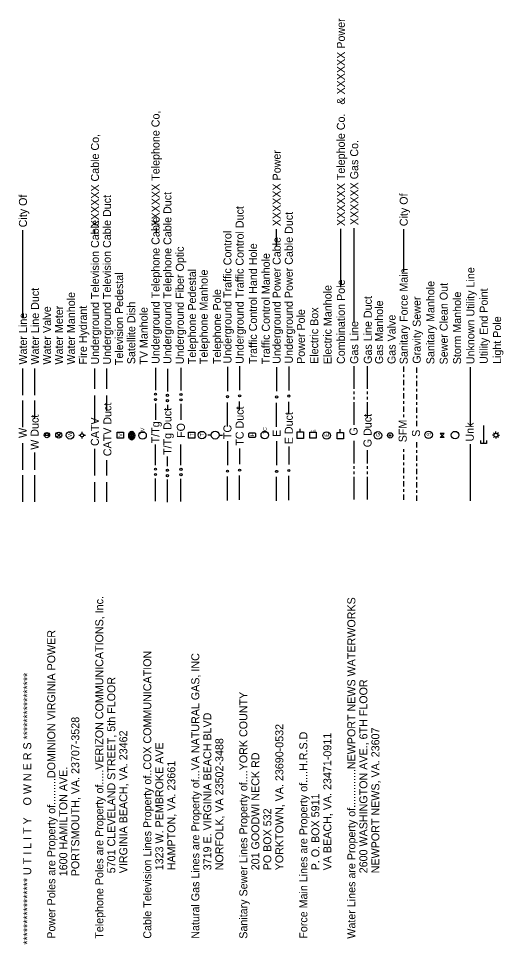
# Model space of a CAD drawing. Extents: x 3872070 to 3879223, y 293944 to 310567.
# Drawn here: x 3876716.5 to 3876898.3, y 293944.3 to 294291.3 of the extents above; entities that cross this region are included whole.
import ezdxf

# ---------------------------------------------------------------- set-up
doc = ezdxf.new("R2010")
doc.units = 0
for name, color, linetype in [('Level 3', 7, 'Continuous'), ('Level 4', 7, 'Continuous'), ('Level 5', 7, 'Continuous'), ('Level 6', 7, 'Continuous'), ('Level 61', 7, 'Continuous'), ('Level 7', 7, 'Continuous'), ('Level 8', 7, 'Continuous'), ('Level 9', 7, 'Continuous')]:
    doc.layers.add(name, color=color, linetype=linetype)

msp = doc.modelspace()

# ---------------------------------------------------------------- linework, layer by layer
at = {"layer": 'Level 4'}
for p, q in [((3876894.75, 294135.14), (3876894.18, 294135.14)), ((3876894.96, 294135.65), (3876894.56, 294136.05)), ((3876894.96, 294134.62), (3876894.56, 294134.22)), ((3876895.48, 294135.86), (3876895.48, 294136.44)), ((3876896.4, 294136.05), (3876895.99, 294135.65)), ((3876896.4, 294134.22), (3876895.99, 294134.62)), ((3876896.2, 294135.14), (3876896.78, 294135.14)), ((3876895.48, 294134.41), (3876895.48, 294133.84))]:
    msp.add_line(p, q, dxfattribs=at)
msp.add_lwpolyline([(3876828.16, 294134.02), (3876825.76, 294134.02), (3876825.76, 294136.21), (3876828.16, 294136.21)], close=True, dxfattribs=at)
for centre, radius in [((3876832.03, 294135.01), 1.41), ((3876895.48, 294135.14), 0.725)]:
    msp.add_circle(centre, radius, dxfattribs=at)
at = {"layer": 'Level 5'}
for p, q in [((3876739.08, 294135.08), (3876739.72, 294135.08)), ((3876740.33, 294135.7), (3876740.33, 294136.33)), ((3876740.96, 294135.08), (3876741.58, 294135.08)), ((3876740.33, 294133.83), (3876740.33, 294134.45))]:
    msp.add_line(p, q, dxfattribs=at)
for centre, radius in [((3876735.83, 294135.08), 1.41), ((3876740.33, 294135.08), 0.625)]:
    msp.add_circle(centre, radius, dxfattribs=at)
at = {"layer": 'Level 6'}
msp.add_lwpolyline([(3876892, 294133.12), (3876892, 294132.03), (3876889.81, 294132.03), (3876889.81, 294133.12)], dxfattribs=at)
msp.add_circle((3876851.27, 294135.04), 1.41, dxfattribs=at)
at = {"layer": 'Level 61'}
for p, q in [((3876718.18, 294179.01), (3876718.18, 294211.9)), ((3876745.18, 294210.45), (3876745.18, 294211.9)), ((3876768.24, 294210.94), (3876768.25, 294212.86)), ((3876813.29, 294205.89), (3876813.29, 294212.31)), ((3876837.36, 294190.56), (3876837.36, 294212.4)), ((3876842.36, 294177.4), (3876842.36, 294212.72)), ((3876860.92, 294196.28), (3876860.92, 294212.33)), ((3876718.18, 294150.13), (3876718.18, 294160.12)), ((3876722.68, 294150.13), (3876722.68, 294160.12)), ((3876745.18, 294152.5), (3876745.18, 294160.12)), ((3876749.68, 294152.5), (3876749.68, 294160.12)), ((3876749.68, 294156.38), (3876749.68, 294160.12)), ((3876767.88, 294160.38), (3876767.88, 294151.96)), ((3876772.34, 294159.95), (3876772.34, 294151.53)), ((3876777.43, 294160.3), (3876777.43, 294151.88)), ((3876794.85, 294160.67), (3876794.85, 294151.67)), ((3876799.41, 294161.02), (3876799.41, 294152.02)), ((3876813.29, 294160.56), (3876813.29, 294151.56)), ((3876817.84, 294160.91), (3876817.84, 294151.91)), ((3876842.36, 294152.46), (3876842.36, 294160.96)), ((3876847.36, 294152.46), (3876847.36, 294160.96)), ((3876860.91, 294158.9), (3876860.91, 294160.88)), ((3876865.9, 294158.47), (3876865.9, 294160.45)), ((3876885.91, 294138.57), (3876885.92, 294160.57)), ((3876860.91, 294156.9), (3876860.91, 294157.9)), ((3876860.91, 294153.9), (3876860.91, 294155.9)), ((3876865.9, 294156.47), (3876865.9, 294157.47)), ((3876865.9, 294153.47), (3876865.9, 294155.47)), ((3876860.91, 294151.9), (3876860.91, 294152.9)), ((3876865.9, 294151.47), (3876865.9, 294152.47)), ((3876745.18, 294139.99), (3876745.18, 294150)), ((3876749.68, 294144.28), (3876749.68, 294150)), ((3876842.36, 294150.46), (3876842.36, 294151.46)), ((3876842.36, 294148.46), (3876842.36, 294149.46)), ((3876847.36, 294150.46), (3876847.36, 294151.46)), ((3876847.36, 294148.46), (3876847.36, 294149.46)), ((3876860.91, 294148.9), (3876860.91, 294150.9)), ((3876865.9, 294148.47), (3876865.9, 294150.47)), ((3876718.18, 294138.13), (3876718.18, 294148.13)), ((3876722.68, 294141.26), (3876722.68, 294148.13)), ((3876767.88, 294146.96), (3876767.88, 294140.93)), ((3876772.34, 294146.53), (3876772.34, 294144.39)), ((3876777.42, 294146.88), (3876777.42, 294140.85)), ((3876794.85, 294138.41), (3876794.85, 294147.41)), ((3876799.41, 294144.49), (3876799.41, 294147.76)), ((3876813.29, 294138.3), (3876813.29, 294147.3)), ((3876817.84, 294143.24), (3876817.85, 294147.65)), ((3876842.36, 294138.96), (3876842.36, 294147.46)), ((3876847.36, 294141.6), (3876847.36, 294147.46)), ((3876860.91, 294146.9), (3876860.91, 294147.9)), ((3876860.91, 294143.9), (3876860.91, 294145.9)), ((3876865.9, 294146.47), (3876865.9, 294147.47)), ((3876865.9, 294143.47), (3876865.9, 294145.47)), ((3876860.91, 294141.9), (3876860.91, 294142.9)), ((3876865.9, 294141.47), (3876865.9, 294142.47)), ((3876865.9, 294138.47), (3876865.9, 294140.47)), ((3876890.9, 294132.03), (3876890.9, 294138.75)), ((3876725.98, 294135.13), (3876727.18, 294135.13)), ((3876726.48, 294135.13), (3876727.88, 294135.13)), ((3876727.18, 294135.13), (3876728.39, 294135.13)), ((3876730.81, 294135.95), (3876731.6, 294135.15)), ((3876730.81, 294134.36), (3876731.6, 294135.15)), ((3876732.4, 294135.95), (3876731.6, 294135.15)), ((3876732.4, 294134.36), (3876731.6, 294135.15)), ((3876788.74, 294135.14), (3876787.54, 294135.14)), ((3876791.74, 294135.14), (3876792.94, 294135.14)), ((3876822.14, 294136.32), (3876822.14, 294137.52)), ((3876837.14, 294136.17), (3876837.14, 294137.37)), ((3876876.04, 294134.3), (3876874.54, 294135.8)), ((3876874.54, 294134.3), (3876876.04, 294135.8)), ((3876876.04, 294135.8), (3876874.54, 294135.8)), ((3876718.18, 294122.13), (3876718.18, 294132.13)), ((3876767.88, 294123.9), (3876767.88, 294131.66)), ((3876777.43, 294123.82), (3876777.42, 294131.58)), ((3876794.85, 294132.93), (3876794.85, 294123.93)), ((3876813.29, 294132.82), (3876813.29, 294123.82)), ((3876842.36, 294124.46), (3876842.36, 294132.96)), ((3876865.9, 294130.47), (3876865.9, 294132.47)), ((3876876.04, 294134.3), (3876874.54, 294134.3)), ((3876885.92, 294110.57), (3876885.92, 294131.72)), ((3876722.68, 294122.13), (3876722.68, 294128.64)), ((3876745.18, 294120.01), (3876745.18, 294130.02)), ((3876799.41, 294130.14), (3876799.41, 294124.28)), ((3876817.85, 294130.88), (3876817.84, 294124.17)), ((3876847.36, 294124.46), (3876847.36, 294129.46)), ((3876860.91, 294128.9), (3876860.91, 294129.9)), ((3876860.91, 294125.9), (3876860.91, 294127.9)), ((3876865.9, 294128.47), (3876865.9, 294129.47)), ((3876749.68, 294120.01), (3876749.68, 294125.8)), ((3876772.34, 294123.47), (3876772.34, 294127.19)), ((3876860.91, 294123.9), (3876860.91, 294124.9)), ((3876865.9, 294125.47), (3876865.9, 294127.47)), ((3876865.9, 294123.47), (3876865.9, 294124.47)), ((3876842.36, 294122.46), (3876842.36, 294123.46)), ((3876842.36, 294120.46), (3876842.36, 294121.46)), ((3876847.36, 294122.46), (3876847.36, 294123.46)), ((3876847.36, 294120.46), (3876847.36, 294121.46)), ((3876860.91, 294120.9), (3876860.91, 294122.9)), ((3876865.9, 294120.47), (3876865.9, 294122.47)), ((3876718.18, 294110.13), (3876718.18, 294120.13)), ((3876722.68, 294110.13), (3876722.68, 294120.13)), ((3876745.18, 294110.13), (3876745.18, 294117.49)), ((3876749.68, 294110.13), (3876749.68, 294117.49)), ((3876767.88, 294110.4), (3876767.88, 294118.9)), ((3876772.34, 294109.97), (3876772.34, 294118.47)), ((3876777.43, 294110.32), (3876777.42, 294118.82)), ((3876794.85, 294110.58), (3876794.85, 294119.65)), ((3876799.41, 294110.93), (3876799.41, 294120)), ((3876813.29, 294110.47), (3876813.29, 294119.54)), ((3876817.84, 294110.82), (3876817.85, 294119.89)), ((3876842.36, 294110.96), (3876842.36, 294119.46)), ((3876847.36, 294110.96), (3876847.36, 294119.46)), ((3876860.91, 294118.9), (3876860.91, 294119.9)), ((3876860.91, 294115.9), (3876860.91, 294117.9)), ((3876865.9, 294118.47), (3876865.9, 294119.47)), ((3876865.9, 294115.47), (3876865.9, 294117.47)), ((3876860.91, 294113.9), (3876860.91, 294114.9)), ((3876865.9, 294113.47), (3876865.9, 294114.47)), ((3876860.91, 294110.89), (3876860.91, 294112.89)), ((3876865.9, 294110.47), (3876865.9, 294112.47))]:
    msp.add_line(p, q, dxfattribs=at)
for points in [[(3876755.86, 294134.01), (3876753.46, 294134.01), (3876753.46, 294136.19), (3876755.86, 294136.19)], [(3876782.58, 294134.05), (3876780.19, 294134.05), (3876780.19, 294136.24), (3876782.58, 294136.24)], [(3876823.34, 294133.92), (3876820.94, 294133.92), (3876820.94, 294136.32), (3876823.34, 294136.32)], [(3876838.34, 294133.77), (3876835.94, 294133.77), (3876835.94, 294136.17), (3876838.34, 294136.17)]]:
    msp.add_lwpolyline(points, close=True, dxfattribs=at)
for centre, radius in [((3876767.88, 294150.46), 0.4), ((3876767.88, 294148.46), 0.4), ((3876772.34, 294150.03), 0.4), ((3876772.34, 294148.03), 0.4), ((3876777.42, 294150.38), 0.4), ((3876777.42, 294148.38), 0.4), ((3876794.85, 294149.54), 0.4), ((3876799.41, 294149.89), 0.4), ((3876813.29, 294149.43), 0.4), ((3876817.84, 294149.78), 0.4), ((3876727.18, 294135.13), 0.98), ((3876731.6, 294135.15), 1.12), ((3876790.24, 294135.14), 1.5), ((3876855.84, 294135.03), 1), ((3876855.84, 294135.03), 0.268), ((3876870.27, 294135.24), 1.41), ((3876880.15, 294135.14), 1.41), ((3876767.88, 294122.4), 0.4), ((3876767.88, 294120.4), 0.4), ((3876772.34, 294121.97), 0.4), ((3876777.42, 294122.32), 0.4), ((3876777.42, 294120.32), 0.4), ((3876794.85, 294121.65), 0.4), ((3876799.41, 294122), 0.4), ((3876813.29, 294121.54), 0.4), ((3876817.84, 294121.89), 0.4), ((3876772.34, 294119.97), 0.4)]:
    msp.add_circle(centre, radius, dxfattribs=at)
msp.add_arc((3876727.18, 294135.13), 0.7, 0.0002, 180.0002, dxfattribs=at)
at = {"layer": 'Level 7'}
msp.add_circle((3876785.3, 294135.14), 1.41, dxfattribs=at)
at = {"layer": 'Level 8'}
for p, q in [((3876758.96, 294134.99), (3876758.02, 294135.92)), ((3876758.02, 294134.05), (3876758.96, 294134.99)), ((3876758.96, 294134.99), (3876758.96, 294136.67)), ((3876758.96, 294134.99), (3876759.9, 294135.92)), ((3876759.9, 294134.05), (3876758.96, 294134.99)), ((3876758.96, 294133.31), (3876758.96, 294134.99))]:
    msp.add_line(p, q, dxfattribs=at)
msp.add_circle((3876763.02, 294135.02), 1.41, dxfattribs=at)
for major_axis, ratio in [((0, 1.68), 0.671774), ((0, 1.23), 0.505061)]:
    msp.add_ellipse((3876758.96, 294134.99), major_axis=major_axis, ratio=ratio, dxfattribs=at)
at = {"layer": 'Level 9'}
msp.add_lwpolyline([(3876805.06, 294134.28), (3876803.15, 294134.28), (3876802.9, 294134.53), (3876802.9, 294135.76), (3876803.15, 294136.01), (3876805.06, 294136.01), (3876805.31, 294135.76), (3876805.31, 294134.53)], close=True, dxfattribs=at)
msp.add_circle((3876808.84, 294135.14), 1.41, dxfattribs=at)

# ---------------------------------------------------------------- texts
at = {"layer": 'Level 3'}
for s, p in [('          Telephone Poles are Property of.....VERIZON COMMUNICATIONS, Inc.        ', (3876748.3, 293935.27)), ('          Water Lines are Property of.............NEWPORT NEWS WATERWORKS', (3876842.8, 293935.27)), ('          Power Poles are Property of.........DOMINION VIRGINIA POWER', (3876730.3, 293935.27)), ('          Cable Television Lines Property of..COX COMMUNICATION      ', (3876766.3, 293935.27)), ('          Natural Gas Lines are Property of...VA NATURAL GAS, INC', (3876784.3, 293935.27)), ('        **************** U T I L I T Y    O W N E R S ****************', (3876721.3, 293935.27)), ('                                5701 CLEVELAND STREET, 5th FLOOR', (3876752.8, 293935.27)), ('                                2600 WASHINGTON AVE., 6TH FLOOR', (3876847.3, 293935.27)), ('          Sanitary Sewer Lines Property of....YORK COUNTY', (3876802.3, 293935.27)), ('                                 3719 E. VIRGINIA BEACH BLVD', (3876788.8, 293935.27)), ('                               PORTSMOUTH, VA. 23707-3528', (3876739.3, 293935.27)), ('                                VIRGINIA BEACH, VA. 23462', (3876757.3, 293935.27)), ('                                 YORKTOWN, VA. 23690-0532', (3876815.8, 293935.27)), ('          Force Main Lines are Property of....H.R.S.D', (3876824.8, 293935.27)), ('                                NEWPORT NEWS, VA. 23607', (3876851.8, 293935.27)), ('                                 NORFOLK, VA 23502-3488', (3876793.3, 293935.27)), ('                                 VA BEACH, VA. 23471-0911', (3876833.8, 293935.27)), ('                                 1323 W. PEMBROKE AVE', (3876770.8, 293935.27)), ('                                 201 GOODWI NECK RD', (3876806.8, 293935.27)), ('                               1600 HAMILTON AVE.', (3876734.8, 293935.27)), ('                                 HAMPTON, VA. 23661   ', (3876775.3, 293935.27)), ('                                 P. O. BOX 5911', (3876829.3, 293935.27)), ('                                 PO BOX 532', (3876811.3, 293935.27))]:
    msp.add_text(s, height=3, rotation=90, dxfattribs=at).set_placement(p)
at = {"layer": 'Level 4'}
for p in [(3876827.73, 294135.94), (3876832.73, 294134.57)]:
    msp.add_text('E', height=1.41, rotation=90, dxfattribs=at).set_placement(p)
at = {"layer": 'Level 5'}
msp.add_text('W', height=1.41, rotation=90, dxfattribs=at).set_placement((3876736.53, 294134.49))
at = {"layer": 'Level 6'}
msp.add_text('G', height=1.41, rotation=90, dxfattribs=at).set_placement((3876851.97, 294134.54))
at = {"layer": 'Level 61'}
for s, height, rotation, p in [(' XXXXXX Telephole Co.   & XXXXXX Power', 3, 90, (3876838.86, 294212.4)), (' XXXXXX Telephone Co,', 3, 90, (3876769.38, 294212.17)), (' XXXXXX Cable Co,', 3, 90, (3876746.68, 294211.9)), (' XXXXXX Gas Co.', 3, 90, (3876843.86, 294212.73)), (' XXXXXX Power', 3, 90, (3876814.79, 294212.31)), (' City Of', 3, 90, (3876719.68, 294211.9)), ('Underground Television Cable Duct', 3, 90, (3876751.18, 294161.58)), ('Underground Telephone Cable Duct', 3, 90, (3876773.84, 294161.81)), (' City Of', 3, 90, (3876862.42, 294212.33)), ('Underground Traffic Control Duct', 3, 90, (3876800.91, 294161.86)), ('Underground Power Cable Duct', 3, 90, (3876819.35, 294161.95)), ('Underground Television Cable', 3, 90, (3876746.68, 294161.58)), ('Underground Telephone Cable', 3, 90, (3876769.38, 294161.85)), ('Underground Traffic Control', 3, 90, (3876796.35, 294162)), ('Underground Power Cable', 3, 90, (3876814.79, 294161.89)), ('Underground Fiber Optic', 3, 90, (3876778.49, 294161.68)), ('Traffic Control Hand Hole', 3, 90, (3876805.91, 294161.77)), ('Traffic Control Manhole', 3, 90, (3876810.72, 294161.67)), ('Telephone Pedestal', 3, 90, (3876783.05, 294161.73)), ('Telephone Manhole', 3, 90, (3876787.45, 294161.73)), ('Sanitary Force Main', 3, 90, (3876862.41, 294161.72)), ('Unknown Utility Line', 3, 90, (3876887.42, 294161.72)), ('Television Pedestal', 3, 90, (3876755.73, 294161.36)), ('Water Line Duct', 3, 90, (3876724.18, 294161.58)), ('Electric Manhole', 3, 90, (3876833.87, 294161.74)), ('Combination Pole', 3, 90, (3876838.86, 294161.79)), ('Sanitary Manhole', 3, 90, (3876872.42, 294161.72)), ('Sewer Clean Out', 3, 90, (3876877.41, 294161.63)), ('Utility End Point', 3, 90, (3876892.42, 294161.82)), ('Water Manhole', 3, 90, (3876737.68, 294161.58)), ('Telephone Pole', 3, 90, (3876792.42, 294161.77)), ('Gas Line Duct', 3, 90, (3876848.96, 294161.83)), ('Gravity Sewer', 3, 90, (3876867.29, 294161.91)), ('Storm Manhole', 3, 90, (3876882.42, 294161.72)), ('Water Valve', 3, 90, (3876728.68, 294161.58)), ('Water Meter', 3, 90, (3876733.18, 294161.58)), ('Fire Hydrant', 3, 90, (3876742.18, 294161.58)), ('Satellite Dish', 3, 90, (3876760.27, 294161.73)), ('Gas Manhole', 3, 90, (3876853.19, 294161.77)), ('Water Line', 3, 90, (3876719.68, 294161.58)), ('TV Manhole', 3, 90, (3876764.92, 294161.52)), ('Power Pole', 3, 90, (3876823.87, 294161.84)), ('Electric Box', 3, 90, (3876828.87, 294161.84)), ('Gas Valve', 3, 90, (3876857.86, 294161.77)), ('Gas Line', 3, 90, (3876843.86, 294161.83)), ('Light Pole', 3, 90, (3876897.42, 294161.82)), ('CATV Duct', 3, 90, (3876751.34, 294127.24)), ('T/Tg Duct', 3, 90, (3876773.84, 294127.73)), ('TC Duct', 3, 90.0011, (3876800.91, 294131.17)), ('W Duct', 3, 90, (3876724.06, 294129.65)), ('CATV', 3, 90, (3876746.64, 294131.06)), ('E Duct', 3, 90.0011, (3876819.34, 294131.73)), ('G Duct', 3, 90, (3876848.86, 294130.6)), ('T/Tg', 3, 90, (3876769.34, 294132.06)), ('FO', 3, 90, (3876778.88, 294134.09)), ('TC', 3, 90, (3876796.35, 294133.64)), ('SFM', 3, 90, (3876862.03, 294132.45)), ('Unk', 3, 90, (3876887.17, 294132.73)), ('W', 3, 90, (3876719.64, 294134.07)), ('V', 1.41, 90, (3876755.44, 294134.52)), ('T', 1.41, 90, (3876782.17, 294134.68)), ('E', 3, 90, (3876814.79, 294134.48)), ('G', 3, 90, (3876843.61, 294134.98)), ('S', 3, 90, (3876867.02, 294134.51)), ('S', 1.41, 90, (3876870.98, 294134.78))]:
    msp.add_text(s, height=height, rotation=rotation, dxfattribs=at).set_placement(p)
at = {"layer": 'Level 7'}
msp.add_text('T', height=1.41, rotation=90, dxfattribs=at).set_placement((3876786, 294134.67))
at = {"layer": 'Level 8'}
msp.add_text('TV', height=1.406, rotation=90, dxfattribs=at).set_placement((3876763.73, 294135.43))
at = {"layer": 'Level 9'}
for s, height, p in [('H', 1.41, (3876804.81, 294134.68)), ('TC', 1.406, (3876809.56, 294135.53))]:
    msp.add_text(s, height=height, rotation=90, dxfattribs=at).set_placement(p)

doc.saveas('drawing.dxf')
